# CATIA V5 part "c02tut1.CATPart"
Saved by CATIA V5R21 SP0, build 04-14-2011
Part number: c02tut1
Bounding box of the stored display mesh (mm): x 0 to 0, y 0 to 120, z 0 to 59.981
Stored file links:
  D:\CATIA V5R21 E-RESOURCES\CATIA-V5R21\catia-v5r21-prt\c02-catia-v5r21-prt\catia-v5r21-tut-1.CATPart
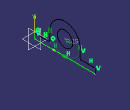
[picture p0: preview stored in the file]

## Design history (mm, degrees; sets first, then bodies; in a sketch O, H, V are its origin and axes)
Body1 (main body)
  Sketch1 on yz-plane, origin (0, 0, 0), H (0, 1, 0), V (0, 0, 1)
    line L1 (0, 0) -> (120, 0)
    line L2 (120, 0) -> (120, 10)
    line L3 (120, 10) -> (90, 10)
    line L4 (90, 10) -> (90, 30)
    arc A1 centre (60, 30) radius 30 from (90, 30) to (30, 30) ccw
    line L5 (30, 30) -> (30, 10)
    point P7 (30, 10)
    line L6 (30, 10) -> (0, 10)
    point P8 (0, 10)
    line L7 (0, 10) -> (0, 0)
    circle A2 centre (60, 30) radius 15
    radius A2 = 15
    horizontal: L1 H, L3 H, L6 H
    vertical: L2 V, L4 V, L7 V
    tangency: A1 L1, A1 L4, L5 A1
    coincidence: P7 L3, P8 V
